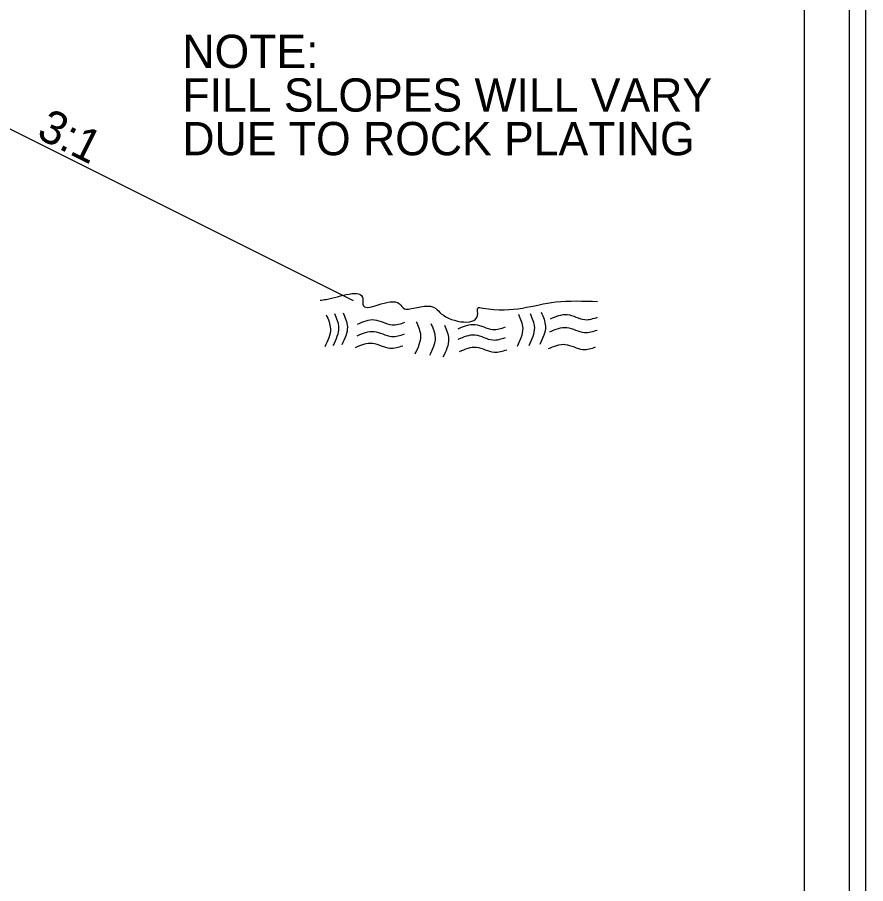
# Model space of a CAD drawing. Extents: x 1734085 to 1734267, y 541107 to 541226.
# Drawn here: x 1734241.04 to 1734266.51, y 541175.16 to 541201.19 of the extents above; entities that cross this region are included whole.
import ezdxf

# ---------------------------------------------------------------- set-up
doc = ezdxf.new("R2010")
doc.units = 0
for name, color, linetype in [('Old_Level_2', 7, 'Continuous'), ('Sheet Plot Border Inside CELL', 7, 'Continuous'), ('Sheet Plot Border Outside CELL', 7, 'Continuous'), ('Sheet Typical CELL', 7, 'Continuous'), ('Typical Slope Point Local CELL', 7, 'Continuous'), ('Typical Text General CELL', 7, 'Continuous')]:
    doc.layers.add(name, color=color, linetype=linetype)

msp = doc.modelspace()

# ---------------------------------------------------------------- linework, layer by layer
at = {"layer": 'Old_Level_2'}
for points in [[(1734250.132, 541192.695), (1734250.318, 541192.717), (1734251.415, 541192.73), (1734251.417, 541192.573), (1734252.513, 541192.586), (1734252.671, 541192.431), (1734252.828, 541192.433), (1734253.611, 541192.442), (1734253.77, 541192.287), (1734254.866, 541192.3), (1734254.864, 541192.456), (1734255.021, 541192.458), (1734257.212, 541192.64), (1734258.46, 541192.655)], [(1734250.315, 541192.256), (1734250.443, 541191.836), (1734250.274, 541191.29)], [(1734250.56, 541192.294), (1734250.688, 541191.874), (1734250.519, 541191.328)], [(1734250.823, 541192.314), (1734250.951, 541191.895), (1734250.782, 541191.349)], [(1734251.257, 541191.977), (1734251.764, 541192.106), (1734252.292, 541191.954), (1734252.677, 541192.029)], [(1734256.087, 541192.27), (1734256.215, 541191.851), (1734256.046, 541191.305)], [(1734256.438, 541192.292), (1734256.565, 541191.872), (1734256.396, 541191.326)], [(1734256.771, 541192.331), (1734256.898, 541191.911), (1734256.729, 541191.365)], [(1734257.045, 541192.132), (1734257.552, 541192.261), (1734258.08, 541192.109), (1734258.466, 541192.184)], [(1734253.019, 541192.042), (1734253.147, 541191.622), (1734252.978, 541191.076)], [(1734253.459, 541191.994), (1734253.586, 541191.574), (1734253.417, 541191.028)], [(1734253.863, 541191.946), (1734253.99, 541191.527), (1734253.821, 541190.981)], [(1734254.276, 541191.837), (1734254.784, 541191.965), (1734255.312, 541191.814), (1734255.697, 541191.888)], [(1734257.032, 541191.746), (1734257.539, 541191.874), (1734258.067, 541191.723), (1734258.452, 541191.797)], [(1734251.243, 541191.626), (1734251.751, 541191.755), (1734252.279, 541191.603), (1734252.664, 541191.678)], [(1734254.28, 541191.521), (1734254.787, 541191.65), (1734255.315, 541191.498), (1734255.7, 541191.573)], [(1734251.195, 541191.275), (1734251.702, 541191.403), (1734252.23, 541191.252), (1734252.615, 541191.326)], [(1734256.985, 541191.237), (1734257.493, 541191.365), (1734258.021, 541191.213), (1734258.406, 541191.288)], [(1734254.319, 541191.153), (1734254.827, 541191.282), (1734255.355, 541191.13), (1734255.74, 541191.204)]]:
    msp.add_spline(points, degree=3, dxfattribs=at)
at = {"layer": 'Sheet Plot Border Inside CELL'}
msp.add_lwpolyline([(1734266.027, 541223.451), (1734086.045, 541223.451), (1734086.045, 541109.5), (1734266.027, 541109.5)], close=True, dxfattribs=at)
at = {"layer": 'Sheet Plot Border Outside CELL'}
msp.add_lwpolyline([(1734266.513, 541225.875), (1734084.641, 541225.875), (1734084.641, 541107.075), (1734266.513, 541107.075)], close=True, dxfattribs=at)
at = {"layer": 'Sheet Typical CELL'}
msp.add_lwpolyline([(1734264.677, 541223.175), (1734102.677, 541223.175), (1734102.677, 541109.775), (1734264.677, 541109.775)], close=True, dxfattribs=at)
at = {"layer": 'Typical Slope Point Local CELL'}
msp.add_line((1734251.133, 541192.674), (1734236.135, 541200.173), dxfattribs=at)

# ---------------------------------------------------------------- texts
msp.add_text('3:1', height=1, rotation=333.435, dxfattribs=at).set_placement((1734241.578, 541197.593))
at = {"layer": 'Typical Text General CELL'}
for s, p in [('NOTE:', (1734245.998, 541199.67)), ('FILL SLOPES WILL VARY', (1734245.998, 541198.359)), ('DUE TO ROCK PLATING', (1734245.998, 541197.048))]:
    msp.add_text(s, height=1, dxfattribs=at).set_placement(p)

doc.saveas('drawing.dxf')
